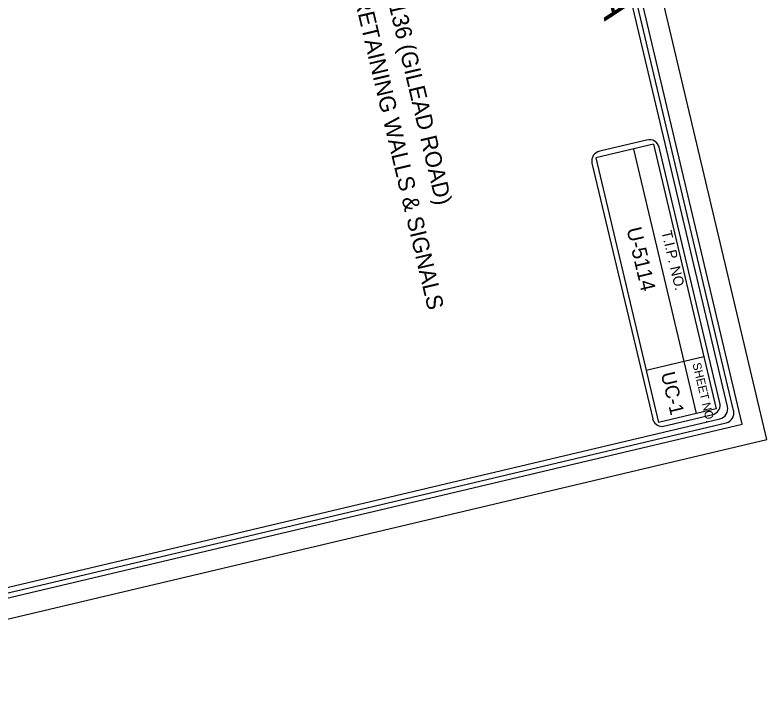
# Model space of a CAD drawing. Extents: x 1439200 to 1640973, y 392611 to 606444.
# Drawn here: x 1442416 to 1445633, y 598050 to 600981 of the extents above; entities that cross this region are included whole.
import ezdxf

# ---------------------------------------------------------------- set-up
doc = ezdxf.new("R2010")
doc.units = 0
doc.layers.add('Level 43', color=7, linetype='Continuous')
doc.layers.add('Old_Level_20', color=7, linetype='Continuous')

msp = doc.modelspace()

# ---------------------------------------------------------------- linework, layer by layer
at = {"layer": 'Level 43'}
for p, q in [((1445118.1, 600446.2), (1444918, 600398.9)), ((1445147.1, 600428), (1444900.5, 600369.6)), ((1445147.1, 600428), (1445415.2, 599295.5)), ((1445431.8, 599321.2), (1445172.2, 600415.3)), ((1445061.8, 600407.8), (1445329.9, 599275.3)), ((1444884.4, 600347.4), (1445144, 599253.3)), ((1444900.5, 600369.6), (1445168.5, 599237.1)), ((1445362.3, 599518.9), (1445115.7, 599460.6)), ((1445415.2, 599295.5), (1445168.5, 599237.1))]:
    msp.add_line(p, q, dxfattribs=at)
msp.add_lwpolyline([(1445632.9, 599164.9), (1443909.8, 606443.8), (1439200, 605328.8), (1440923.1, 598050)], close=True, dxfattribs=at)
for points in [[(1445490.4, 599289.4), (1443990.3, 605626.4)], [(1445463.9, 599305.8), (1444024.6, 605385.7)], [(1441856, 598406.5), (1445431.2, 599252.8)], [(1445184.6, 599220.8), (1445406.7, 599273.4)], [(1441047.6, 598192.5), (1445457.7, 599236.5)]]:
    msp.add_lwpolyline(points, dxfattribs=at)
for centre in [(1445421.3, 599295.7), (1445447.8, 599279.3)]:
    msp.add_arc(centre, 44, 283.3181, 13.3181, dxfattribs=at)
for centre, major_axis, ratio, start_param, end_param in [((1445128.1, 600405), (43.9, 10.4), 0.941469, 0.000468, 1.571265), ((1444928.1, 600357.5), (-43.9, -10.4), 0.941469, 4.712857, 6.283654), ((1445387.7, 599310.8), (43.9, 10.4), 0.926296, 4.933032, 6.283554), ((1445187.7, 599263.4), (-43.9, -10.4), 0.941469, 0.000472, 1.282481)]:
    msp.add_ellipse(centre, major_axis=major_axis, ratio=ratio, start_param=start_param, end_param=end_param, dxfattribs=at)
at = {"layer": 'Old_Level_20'}
msp.add_lwpolyline([(1439298.8, 605293.4), (1440988.4, 598155.9), (1445527, 599230.3), (1443837.3, 606367.8)], close=True, dxfattribs=at)

# ---------------------------------------------------------------- texts
at = {"layer": 'Level 43'}
for s, height, rotation, p in [('STATE OF NORTH CAROLINA', 135.18, 283.3466, (1444349.2, 603434.4)), ('TYPE OF WORK: GRADING, PAVING, DRAINAGE, RETAINING WALLS & SIGNALS', 70.155, 283.3038, (1443358.5, 603204.5)), ('LOCATION: US-21 (STATESVILLE ROAD) AND SR 2136 (GILEAD ROAD)', 70.155, 283.3038, (1443493.9, 603227)), ('U-5114', 63.64, 283.3466, (1445031.8, 600065.5)), ('T.I.P. NO.', 43.92, 283.3466, (1445181.2, 600053.6)), ('SHEET NO.', 36.29, 283.3466, (1445313.9, 599488.8)), ('UC-1', 59.89, 283.3466, (1445178.7, 599446.7))]:
    msp.add_text(s, height=height, rotation=rotation, dxfattribs=at).set_placement(p)

doc.saveas('drawing.dxf')
